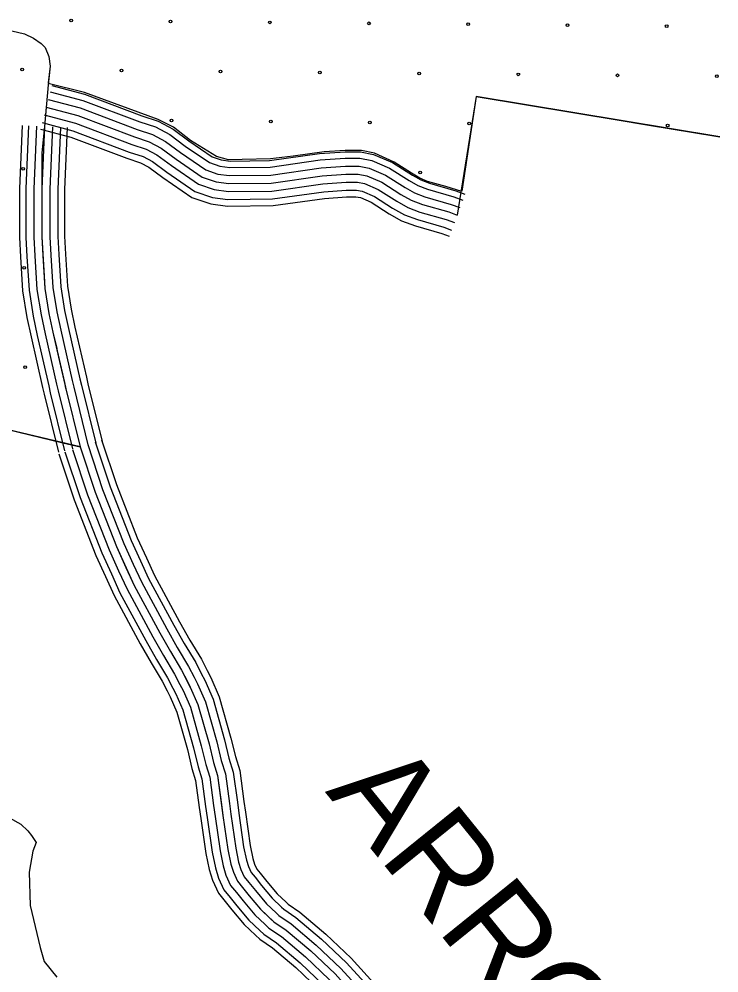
# Model space of a CAD drawing. Extents: x 1551132 to 1791609, y 378168 to 563823.
# Drawn here: x 1609512 to 1612224, y 433242 to 436940 of the extents above; entities that cross this region are included whole.
import ezdxf

# ---------------------------------------------------------------- set-up
doc = ezdxf.new("R2010")
doc.units = 0
for name, color, linetype in [('DESIGN - EROSION CONTROL - Devices', 7, 'Continuous'), ('DESIGN - ROW - Right-of-Way and Easement Labels', 7, 'Continuous'), ('DESIGN - SCRATCH - User 1', 7, 'Continuous'), ('DESIGN - TRANSPORTATION - Text', 7, 'Continuous'), ('SURVEY - DRAINAGE - Area Shapes', 7, 'Continuous'), ('SURVEY - TRANSPORTATION - Roads', 7, 'Continuous'), ('SURVEY - VEGETATION - Features with Text', 7, 'Continuous')]:
    doc.layers.add(name, color=color, linetype=linetype)

msp = doc.modelspace()

# ---------------------------------------------------------------- linework, layer by layer
at = {"layer": 'DESIGN - EROSION CONTROL - Devices'}
msp.add_line((1611283.606, 436640.018), (1611209.983, 436180.281), dxfattribs=at)
msp.add_line((1611283.606, 436640.018), (1611209.983, 436180.281), dxfattribs=at)
for centre in [(1609714.559, 436935.054), (1609714.559, 436935.054), (1610099.112, 436931.321), (1610099.112, 436931.321), (1610483.665, 436927.587), (1610483.665, 436927.587), (1610868.218, 436923.853), (1610868.218, 436923.853), (1611252.771, 436920.12), (1611252.771, 436920.12), (1611637.324, 436916.386), (1611637.324, 436916.386), (1612021.877, 436912.653), (1612021.877, 436912.653), (1609524.15, 436744.644), (1609524.15, 436744.644), (1609908.703, 436740.911), (1609908.703, 436740.911), (1610293.256, 436737.177), (1610293.256, 436737.177), (1610677.808, 436733.444), (1610677.808, 436733.444), (1611062.361, 436729.71), (1611062.361, 436729.71), (1611446.914, 436725.977), (1611446.914, 436725.977), (1611831.467, 436722.243), (1611831.467, 436722.243), (1612216.02, 436718.51), (1612216.02, 436718.51), (1610102.846, 436546.768), (1610102.846, 436546.768), (1610487.399, 436543.034), (1610487.399, 436543.034), (1610871.952, 436539.301), (1610871.952, 436539.301), (1611256.505, 436535.567), (1611256.505, 436535.567), (1612025.611, 436528.1), (1612025.611, 436528.1), (1609527.883, 436360.091), (1609527.883, 436360.091), (1611066.095, 436345.157), (1611066.095, 436345.157), (1609531.617, 435975.538), (1609531.617, 435975.538), (1609535.35, 435590.985), (1609535.35, 435590.985)]:
    msp.add_circle(centre, 5.28, dxfattribs=at)
at = {"layer": 'DESIGN - SCRATCH - User 1'}
msp.add_line((1611283.606, 436640.018), (1611227.616, 436273.617), dxfattribs=at)
for points in [[(1611227.616, 436271.492), (1611165.484, 436290.567), (1611094.894, 436311.043), (1611065.244, 436323.76), (1611032.77, 436343.535), (1610966.405, 436385.92), (1610890.165, 436419.821), (1610839.333, 436431.121), (1610775.793, 436431.121), (1610693.903, 436425.471), (1610573.889, 436408.52), (1610486.35, 436398.628), (1610376.219, 436395.803), (1610323.978, 436394.395), (1610277.38, 436407.103), (1610177.14, 436469.263), (1610110.775, 436521.531), (1610051.477, 436550.49), (1609766.267, 436655.026), (1609625.078, 436690.344)], [(1612227.251, 436484.006), (1611283.606, 436640.018)], [(1609617.237, 436598.833), (1609611.079, 436523.322), (1609600.295, 436421.153), (1609600.345, 436281.674), (1609600.345, 436095.761), (1609612.387, 435895.731), (1609627.694, 435799.362), (1609643.186, 435727.06), (1609665.56, 435629.041), (1609693.618, 435506.096), (1609748.841, 435281.657)], [(1609748.841, 435281.657), (1609142.806, 435425.027)]]:
    msp.add_lwpolyline(points, dxfattribs=at)
at = {"layer": 'DESIGN - TRANSPORTATION - Text'}
msp.add_lwpolyline([(1609474.772, 433843.369), (1609518.562, 433818.868), (1609546.32, 433792.526), (1609560.153, 433774.342), (1609577.911, 433748.108), (1609565.57, 433714.166), (1609550.762, 433632.147), (1609555.511, 433503.835), (1609593.952, 433341.097), (1609609.435, 433286.829), (1609658.875, 433226.194)], dxfattribs=at)
at = {"layer": 'SURVEY - DRAINAGE - Area Shapes'}
for points in [[(1609205.613, 436934.741), (1609369.526, 436908.232), (1609483.632, 436895.282), (1609533.631, 436882.849), (1609567.563, 436866.54), (1609597.471, 436846.248), (1609613.379, 436830.081), (1609627.145, 436795.88), (1609632.87, 436757.737), (1609625.262, 436693.652)], [(1609205.613, 436934.741), (1609369.526, 436908.232), (1609483.632, 436895.282), (1609533.631, 436882.849), (1609567.563, 436866.54), (1609597.471, 436846.248), (1609613.379, 436830.081), (1609627.145, 436795.88), (1609632.87, 436757.737), (1609624.312, 436685.627), (1609611.079, 436523.322), (1609607.929, 436493.472)], [(1609633.228, 436658.734), (1609758.775, 436625.209), (1609979.612, 436541.89), (1610041.377, 436521.898), (1610096.084, 436492.514), (1610156.332, 436447.763), (1610249.839, 436383.786), (1610289.896, 436369.902), (1610329.203, 436364.702), (1610484.975, 436366.677), (1610679.595, 436394.161), (1610776.476, 436401.445), (1610832.65, 436400.795), (1610878.624, 436392.111), (1610947.322, 436362.711), (1611023.77, 436313.893), (1611057.97, 436294.551), (1611095.01, 436280.567), (1611196.625, 436251.358), (1611231.532, 436238.416)], [(1609639.611, 436682.618), (1609766.342, 436648.776), (1609987.786, 436565.224), (1610051.11, 436544.723), (1610109.367, 436513.431), (1610170.682, 436467.888), (1610261.055, 436406.053), (1610295.621, 436394.078), (1610330.67, 436389.444), (1610483.083, 436391.378), (1610676.937, 436418.745), (1610775.693, 436426.179), (1610835.108, 436425.487), (1610885.865, 436415.895), (1610958.914, 436384.628), (1611036.512, 436335.085), (1611068.478, 436317.001), (1611102.802, 436304.051), (1611204.349, 436274.859), (1611240.132, 436261.592)], [(1609625.237, 436628.784), (1609749.275, 436595.658), (1609969.362, 436512.622), (1610029.177, 436493.264), (1610079.418, 436466.28), (1610138.333, 436422.512), (1610235.756, 436355.86), (1610282.713, 436339.576), (1610327.353, 436333.676), (1610487.35, 436335.71), (1610682.928, 436363.319), (1610777.46, 436370.436), (1610829.575, 436369.828), (1610869.541, 436362.277), (1610932.781, 436335.21), (1611007.787, 436287.317), (1611044.787, 436266.392), (1611085.244, 436251.125), (1611186.941, 436221.891), (1611220.757, 436209.349)], [(1609617.237, 436598.833), (1609739.784, 436566.107), (1609959.112, 436483.355), (1610016.969, 436464.63), (1610062.751, 436440.037), (1610120.333, 436397.27), (1610221.681, 436327.926), (1610275.53, 436309.259), (1610325.512, 436302.65), (1610489.725, 436304.734), (1610686.262, 436332.485), (1610778.443, 436339.418), (1610826.492, 436338.86), (1610860.458, 436332.443), (1610918.248, 436307.709), (1610991.804, 436260.741), (1611031.603, 436238.233), (1611075.469, 436221.674), (1611177.258, 436192.415), (1611209.983, 436180.281)], [(1609617.237, 436598.833), (1609739.784, 436566.107), (1609959.112, 436483.355), (1610016.969, 436464.63), (1610062.751, 436440.037), (1610120.333, 436397.27), (1610221.681, 436327.926), (1610275.53, 436309.259), (1610325.512, 436302.65), (1610489.725, 436304.734), (1610686.262, 436332.485), (1610778.443, 436339.418), (1610826.492, 436338.86), (1610860.458, 436332.443), (1610918.248, 436307.709), (1610991.804, 436260.741), (1611031.603, 436238.233), (1611075.469, 436221.674), (1611177.258, 436192.415), (1611209.983, 436180.281)], [(1609601.246, 436538.931), (1609720.793, 436507.005), (1609938.613, 436424.82), (1609992.561, 436407.361), (1610029.419, 436387.561), (1610084.334, 436346.776), (1610193.523, 436272.066), (1610261.163, 436248.616), (1610321.82, 436240.599), (1610494.474, 436242.791), (1610692.928, 436270.808), (1610780.409, 436277.392), (1610820.333, 436276.925), (1610842.291, 436272.775), (1610889.173, 436252.708), (1610959.838, 436207.59), (1611005.237, 436181.914), (1611055.928, 436162.781), (1611157.892, 436133.472), (1611188.433, 436122.146)], [(1609609.237, 436568.882), (1609730.293, 436536.556), (1609948.862, 436454.088), (1610004.761, 436435.995), (1610046.085, 436413.795), (1610102.334, 436372.027), (1610207.606, 436299.992), (1610268.346, 436278.941), (1610323.67, 436271.625), (1610492.099, 436273.758), (1610689.595, 436301.651), (1610779.426, 436308.401), (1610823.408, 436307.893), (1610851.374, 436302.609), (1610903.715, 436280.209), (1610975.821, 436234.166), (1611018.42, 436210.073), (1611065.694, 436192.223), (1611167.575, 436162.939), (1611199.208, 436151.214)], [(1609524.447, 436527.173), (1609513.631, 436283.599), (1609513.631, 436093.153), (1609518.13, 436018.468)], [(1609549.138, 436526.073), (1609538.347, 436283.049), (1609538.347, 436093.895), (1609542.797, 436019.959)], [(1609580.113, 436524.698), (1609569.346, 436282.366), (1609569.346, 436094.828), (1609573.746, 436021.818)], [(1609594.604, 436514.081), (1609712.918, 436482.488), (1609930.113, 436400.544), (1609982.436, 436383.611), (1610015.602, 436365.794), (1610069.401, 436325.834), (1610181.848, 436248.891), (1610255.213, 436223.465), (1610320.295, 436214.857), (1610496.441, 436217.09), (1610695.695, 436245.224), (1610781.226, 436251.658), (1610817.775, 436251.233), (1610834.758, 436248.024), (1610877.115, 436229.899), (1610946.58, 436185.539), (1610994.304, 436158.555), (1611047.82, 436138.355), (1611149.859, 436109.021), (1611179.492, 436098.037)], [(1609611.079, 436523.322), (1609600.345, 436281.674), (1609600.345, 436095.761), (1609612.387, 435895.731), (1609627.694, 435799.362), (1609643.186, 435727.06), (1609693.618, 435506.096), (1609748.833, 435281.69)], [(1609611.079, 436523.322), (1609600.345, 436281.674), (1609600.345, 436095.761), (1609604.687, 436023.684)], [(1609642.045, 436521.947), (1609631.345, 436280.983), (1609631.345, 436096.695), (1609635.628, 436025.551)], [(1609673.019, 436520.572), (1609662.344, 436280.299), (1609662.344, 436097.628), (1609666.577, 436027.41)], [(1609698.71, 436519.431), (1609688.06, 436279.724), (1609688.06, 436098.403), (1609692.243, 436028.96)], [(1609573.746, 436021.843), (1609581.537, 435892.364), (1609597.212, 435793.678), (1609612.92, 435720.36), (1609657.527, 435524.896)], [(1609604.687, 436023.701), (1609612.387, 435895.731), (1609627.694, 435799.362), (1609643.186, 435727.06), (1609687.751, 435531.797)], [(1609635.628, 436025.559), (1609643.236, 435899.098), (1609658.177, 435805.045), (1609673.452, 435733.76), (1609717.976, 435538.697)], [(1609666.577, 436027.426), (1609674.093, 435902.473), (1609688.668, 435810.729), (1609703.718, 435740.452), (1609748.191, 435545.597)], [(1609692.243, 436028.968), (1609699.685, 435905.273), (1609713.951, 435815.446), (1609728.834, 435746.011), (1609773.266, 435551.314)], [(1609518.13, 436018.493), (1609526.08, 435886.306), (1609542.421, 435783.461), (1609558.513, 435708.326), (1609603.212, 435512.496)], [(1609542.797, 436019.976), (1609550.68, 435888.989), (1609566.721, 435787.995), (1609582.654, 435713.668), (1609627.311, 435517.996)], [(1609748.2, 435545.605), (1609753.95, 435520.396), (1609809.04, 435296.507)], [(1609773.266, 435551.322), (1609778.966, 435526.33), (1609834.006, 435302.649)], [(1609603.212, 435512.529), (1609609.236, 435486.087), (1609664.627, 435260.973)], [(1609627.303, 435518.021), (1609633.286, 435491.795), (1609688.626, 435266.873)], [(1609657.527, 435524.921), (1609663.452, 435498.946), (1609718.734, 435274.282)], [(1609687.751, 435531.813), (1609693.618, 435506.096), (1609748.833, 435281.69)], [(1609717.976, 435538.705), (1609723.784, 435513.246), (1609778.932, 435289.099)]]:
    msp.add_lwpolyline(points, dxfattribs=at)
at = {"layer": 'SURVEY - TRANSPORTATION - Roads'}
for points in [[(1609748.833, 435281.69), (1609806.832, 435106.185), (1609889.396, 434894.988), (1609958.394, 434744.051), (1610057.2, 434560.805), (1610098.733, 434488.286), (1610142.265, 434415.751), (1610175.572, 434350.224), (1610205.38, 434282.914), (1610248.312, 434130.185), (1610265.803, 434057.858), (1610281.461, 434007.607), (1610302.344, 433853.053), (1610321.385, 433720.566), (1610332.985, 433664.331), (1610342.76, 433632.172), (1610358.534, 433597.963), (1610378.384, 433573.737), (1610404.192, 433541.453), (1610447.874, 433488.969), (1610499.606, 433440.434), (1610547.446, 433407.966), (1610642.794, 433327.189), (1610736.509, 433238.02)], [(1609748.833, 435281.69), (1609806.832, 435106.185), (1609889.396, 434894.988), (1609926.145, 434814.595)], [(1609778.266, 435291.415), (1609836.006, 435116.702), (1609917.954, 434907.089), (1609954.336, 434827.487)], [(1609807.698, 435301.149), (1609865.18, 435127.219), (1609946.503, 434919.181), (1609982.536, 434840.37)], [(1609832.114, 435309.216), (1609889.38, 435135.936), (1609970.194, 434929.223), (1610005.918, 434851.062)], [(1609666.502, 435254.481), (1609725.225, 435076.768), (1609809.523, 434861.146), (1609847.28, 434778.544)], [(1609689.968, 435262.231), (1609748.483, 435085.152), (1609832.289, 434870.796), (1609869.755, 434788.819)], [(1609719.4, 435271.965), (1609777.657, 435095.669), (1609860.838, 434882.888), (1609897.954, 434801.703)], [(1609982.536, 434840.379), (1610013.935, 434771.685), (1610111.391, 434590.931), (1610152.215, 434519.654), (1610196.547, 434445.793), (1610218.413, 434402.776)], [(1610005.918, 434851.071), (1610036.968, 434783.144), (1610133.874, 434603.423), (1610174.406, 434532.662), (1610219.055, 434458.252), (1610241.338, 434414.426)], [(1609897.954, 434801.711), (1609930.628, 434730.234), (1610030.101, 434545.738), (1610071.992, 434472.602), (1610115.124, 434400.734), (1610135.515, 434360.625)], [(1609926.145, 434814.603), (1609958.394, 434744.051), (1610057.2, 434560.805), (1610098.733, 434488.286), (1610142.265, 434415.751), (1610163.148, 434374.675)], [(1609954.336, 434827.495), (1609986.16, 434757.868), (1610084.3, 434575.872), (1610125.474, 434503.97), (1610169.406, 434430.768), (1610190.78, 434388.725)], [(1609847.28, 434778.552), (1609880.713, 434705.4), (1609981.402, 434518.67), (1610023.926, 434444.418), (1610066.35, 434373.733), (1610085.849, 434335.374)], [(1609869.755, 434788.827), (1609902.854, 434716.417), (1610003.01, 434530.679), (1610045.251, 434456.919), (1610087.983, 434385.708), (1610107.882, 434346.574)], [(1610218.413, 434402.784), (1610231.588, 434376.842), (1610263.862, 434303.965), (1610308.302, 434145.869), (1610325.594, 434074.384), (1610342.202, 434021.074), (1610358.068, 433903.671)], [(1610241.338, 434414.434), (1610254.829, 434387.884), (1610288.12, 434312.698), (1610333.194, 434152.369), (1610350.393, 434081.242), (1610367.401, 434026.666), (1610383.551, 433907.121)], [(1610135.507, 434360.65), (1610147.565, 434336.916), (1610176.139, 434272.389), (1610218.313, 434122.343), (1610235.912, 434049.591), (1610251.087, 434000.873), (1610265.912, 433891.221)], [(1610163.139, 434374.692), (1610175.572, 434350.224), (1610205.38, 434282.914), (1610248.312, 434130.185), (1610265.803, 434057.858), (1610281.461, 434007.607), (1610296.628, 433895.371)], [(1610190.772, 434388.734), (1610203.58, 434363.533), (1610234.621, 434293.439), (1610278.312, 434138.027), (1610295.694, 434066.125), (1610311.836, 434014.341), (1610327.344, 433899.521)], [(1610085.833, 434335.407), (1610097.224, 434312.998), (1610123.582, 434253.472), (1610164.406, 434108.251), (1610182.18, 434034.741), (1610196.505, 433988.765), (1610210.696, 433883.754)], [(1610107.866, 434346.599), (1610119.557, 434323.607), (1610146.898, 434261.864), (1610188.322, 434114.501), (1610206.013, 434041.333), (1610220.721, 433994.14), (1610235.187, 433887.07)], [(1610210.696, 433883.779), (1610216.463, 433841.078), (1610235.929, 433705.624), (1610248.862, 433642.914), (1610261.52, 433601.263), (1610284.436, 433551.578), (1610310.977, 433519.178), (1610336.993, 433486.635), (1610384.65, 433429.384), (1610427.791, 433388.908)], [(1610235.187, 433887.087), (1610240.937, 433844.494), (1610260.287, 433709.883), (1610272.836, 433649.023), (1610284.678, 433610.072), (1610305.552, 433564.795), (1610330.193, 433534.728), (1610356.151, 433502.26), (1610402.667, 433446.367), (1610444.699, 433406.941)], [(1610265.903, 433891.237), (1610271.645, 433848.77), (1610290.836, 433715.224), (1610302.911, 433656.673), (1610313.719, 433621.122), (1610332.043, 433581.379), (1610354.284, 433554.237), (1610380.167, 433521.853), (1610425.274, 433467.668), (1610465.907, 433429.55)], [(1610296.628, 433895.387), (1610302.344, 433853.053), (1610321.385, 433720.566), (1610332.985, 433664.331), (1610342.76, 433632.172), (1610358.534, 433597.963), (1610378.384, 433573.737), (1610404.192, 433541.453), (1610447.874, 433488.969), (1610487.115, 433452.159)], [(1610327.352, 433899.538), (1610333.043, 433857.336), (1610351.935, 433725.908), (1610363.059, 433671.99), (1610371.801, 433643.223), (1610385.025, 433614.547), (1610402.483, 433593.238), (1610428.216, 433561.054), (1610470.473, 433510.269), (1610508.322, 433474.768)], [(1610358.068, 433903.688), (1610363.751, 433861.612), (1610382.484, 433731.25), (1610393.134, 433679.64), (1610400.842, 433654.273), (1610411.516, 433631.131), (1610426.574, 433612.747), (1610452.232, 433580.646), (1610493.081, 433531.57), (1610529.53, 433497.377)], [(1610383.551, 433907.129), (1610389.217, 433865.162), (1610407.825, 433735.683), (1610418.075, 433685.99), (1610424.933, 433663.44), (1610433.491, 433644.881), (1610446.566, 433628.922), (1610472.165, 433596.905), (1610511.831, 433549.245), (1610547.122, 433516.136)], [(1610547.105, 433516.144), (1610554.58, 433509.136), (1610600.57, 433477.918), (1610701.426, 433392.483), (1610799.29, 433299.364), (1610898.538, 433190.094), (1610918.246, 433165.694)], [(1610508.306, 433474.777), (1610519.03, 433464.718), (1610566.221, 433432.692), (1610663.51, 433350.265), (1610758.691, 433259.704), (1610855.447, 433153.168), (1610874.13, 433130.051)], [(1610529.514, 433497.385), (1610538.463, 433488.994), (1610584.996, 433457.409), (1610684.235, 433373.341), (1610780.883, 433281.38), (1610878.997, 433173.352), (1610898.238, 433149.527)], [(1610487.098, 433452.168), (1610499.606, 433440.434), (1610547.446, 433407.966), (1610642.794, 433327.189), (1610736.509, 433238.02), (1610831.898, 433132.993), (1610850.014, 433110.567)], [(1610444.682, 433406.95), (1610460.748, 433391.874), (1610509.897, 433358.523), (1610601.353, 433281.038), (1610692.135, 433194.661), (1610784.799, 433092.633), (1610801.79, 433071.608)], [(1610465.89, 433429.559), (1610480.181, 433416.15), (1610528.672, 433383.241), (1610622.078, 433304.114), (1610714.326, 433216.337), (1610808.348, 433112.817), (1610825.898, 433091.083)], [(1610427.774, 433388.916), (1610445.257, 433372.515), (1610494.923, 433338.806), (1610584.837, 433262.638), (1610674.443, 433177.377), (1610766.024, 433076.541), (1610782.557, 433056.074)]]:
    msp.add_lwpolyline(points, dxfattribs=at)
at = {"layer": 'SURVEY - VEGETATION - Features with Text'}
msp.add_line((1611283.606, 436640.018), (1611209.983, 436180.281), dxfattribs=at)
for points in [[(1611283.606, 436640.018), (1611241.857, 436379.345)], [(1611283.606, 436640.018), (1611544.067, 436596.959)], [(1611283.606, 436640.018), (1612227.251, 436484.006)], [(1609617.237, 436598.833), (1609611.079, 436523.322), (1609600.295, 436421.153), (1609600.345, 436281.674), (1609600.345, 436095.761), (1609612.387, 435895.731), (1609627.694, 435799.362), (1609643.186, 435727.06), (1609665.56, 435629.041), (1609693.618, 435506.096), (1609748.841, 435281.657)], [(1609617.237, 436598.833), (1609611.079, 436523.322), (1609600.295, 436421.153), (1609600.329, 436335.643)], [(1609617.237, 436598.833), (1609739.784, 436566.107), (1609959.112, 436483.355), (1610016.969, 436464.63), (1610062.751, 436440.037), (1610120.333, 436397.27), (1610221.681, 436327.926), (1610275.53, 436309.259), (1610325.512, 436302.65), (1610489.725, 436304.734), (1610686.262, 436332.485), (1610778.443, 436339.418), (1610826.492, 436338.86), (1610860.458, 436332.443), (1610918.248, 436307.709), (1610991.804, 436260.741), (1611031.603, 436238.233), (1611075.469, 436221.674), (1611177.258, 436192.415), (1611209.983, 436180.281)], [(1611692.055, 436572.492), (1611952.507, 436529.424)], [(1611952.507, 436529.424), (1612212.968, 436486.365)], [(1609600.345, 436185.639), (1609600.345, 436095.761), (1609610.812, 435921.948)], [(1609610.812, 435921.948), (1609612.387, 435895.731), (1609627.694, 435799.362), (1609643.186, 435727.06), (1609657.919, 435662.5)], [(1609691.301, 435516.255), (1609693.618, 435506.096), (1609748.841, 435281.657)], [(1609022.833, 435456.361), (1609748.841, 435281.657)], [(1609425.332, 435359.5), (1609682.001, 435297.74)], [(1609682.001, 435297.74), (1609748.841, 435281.657)]]:
    msp.add_lwpolyline(points, dxfattribs=at)

# ---------------------------------------------------------------- texts
at = {"layer": 'DESIGN - ROW - Right-of-Way and Easement Labels'}
msp.add_text('ARROW', height=370.0022, rotation=308.9384, dxfattribs=at).set_placement((1610696.268, 433944.797))

doc.saveas('drawing.dxf')
